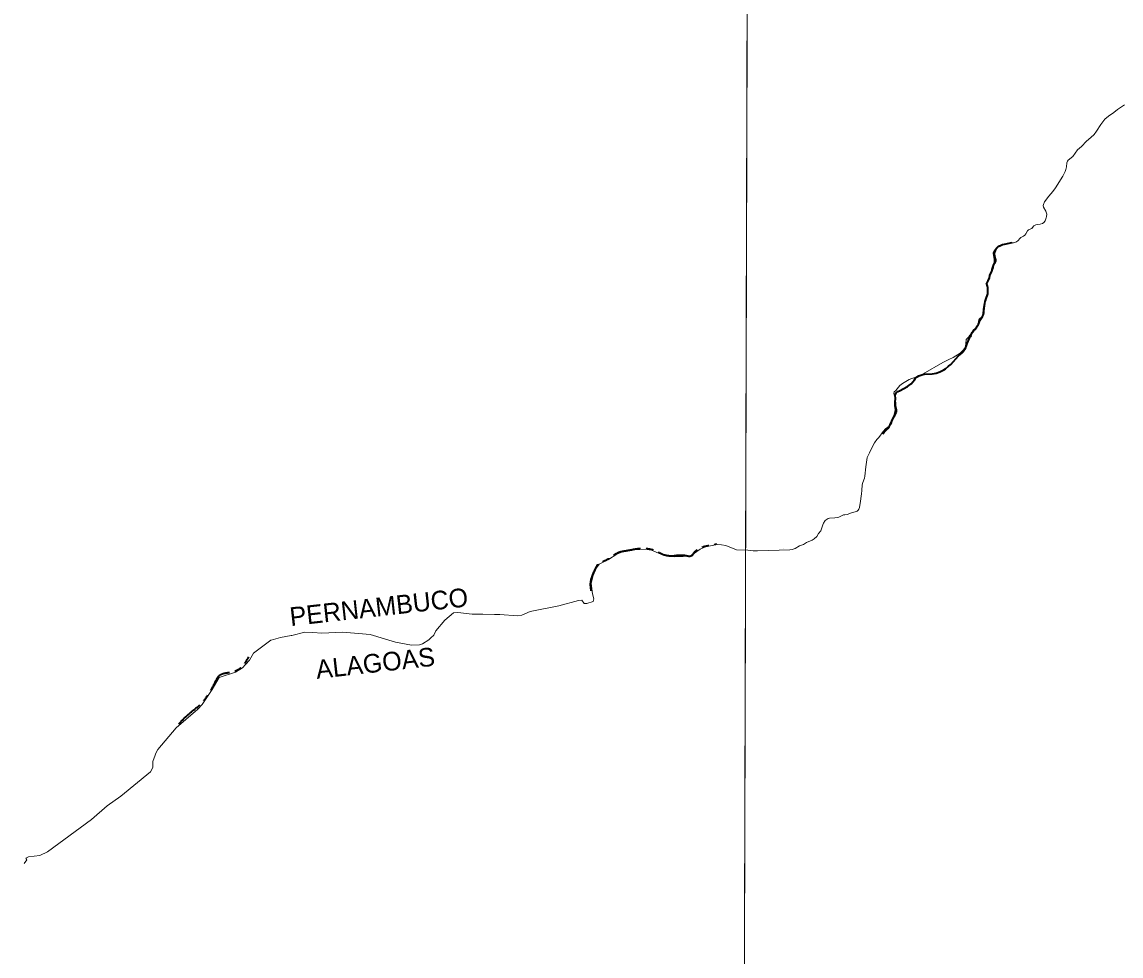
# Model space of a CAD drawing. Extents: x 553962 to 842807, y 8883888 to 9032388.
# Drawn here: x 582541 to 587242, y 8915855 to 8919850 of the extents above; entities that cross this region are included whole.
import ezdxf
from ezdxf.enums import TextEntityAlignment as Align

# ---------------------------------------------------------------- set-up
doc = ezdxf.new("R2010")
doc.units = 0
doc.header["$LTSCALE"] = 20
doc.header["$PDMODE"] = 32
doc.header["$PDSIZE"] = 10
doc.linetypes.add('LONG_DASH_SHORT_DASH', pattern=[9.9, 6, -1.2, 1.5, -1.2])
doc.layers.add('6', color=7, linetype='Continuous', lineweight=13)

msp = doc.modelspace()

# ---------------------------------------------------------------- linework, layer by layer
at = {"layer": '6', "linetype": 'LONG_DASH_SHORT_DASH', "lineweight": 35}
msp.add_line((585799.02, 8917597.87), (585799.32, 8917597.75), dxfattribs=at)
at = {"layer": '6'}
for points in [[(585656.26, 8924738.82), (585614.83, 8909969.81), (585573.59, 8896026.67)], [(586916.89, 8918999.45), (586921.84, 8919011.65), (586923.22, 8919017.85), (586923.79, 8919027.85), (586919.88, 8919040.65), (586909.88, 8919057.05), (586909.01, 8919064.25), (586909.36, 8919069.65), (586914.44, 8919080.45), (586932.36, 8919104.25), (586949.8, 8919125.05), (586961.45, 8919140.25), (586992.81, 8919190.24), (587002.74, 8919209.44), (587006.17, 8919218.44), (587008.87, 8919230.44), (587010.37, 8919247.44), (587012.94, 8919254.64), (587015.99, 8919258.64), (587034.99, 8919274.84), (587055.59, 8919302.44), (587071.97, 8919316.44), (587094.02, 8919340.44), (587112.31, 8919355.24), (587126.07, 8919368.84), (587137.1, 8919382.04), (587155.14, 8919411.03), (587172.63, 8919433.83), (587187.38, 8919446.23), (587211.42, 8919462.03), (587226.22, 8919474.83), (587234.77, 8919481.43), (587255.95, 8919495.03)], [(586679.62, 8918760.47), (586680.31, 8918772.47), (586692.49, 8918786.46), (586696.8, 8918798.86), (586696.92, 8918809.26), (586697.68, 8918812.66), (586699.34, 8918815.26), (586704.18, 8918820.06), (586707.65, 8918826.86), (586707.43, 8918834.46), (586702.57, 8918847.66), (586701.75, 8918857.46), (586703.12, 8918864.06), (586709.7, 8918881.26), (586720.99, 8918893.46), (586725.89, 8918895.66), (586766.08, 8918904.86), (586782.19, 8918905.06), (586794.27, 8918909.06), (586801.82, 8918914.66), (586808.77, 8918923.26), (586812.98, 8918927.26), (586824.34, 8918933.86), (586830.05, 8918938.46), (586834.77, 8918944.06), (586841.92, 8918955.86), (586845.78, 8918960.26), (586848.85, 8918962.45), (586859.67, 8918966.85), (586863.65, 8918970.45), (586869.35, 8918977.45), (586877.18, 8918981.65), (586883.62, 8918984.05), (586895.7, 8918985.25), (586905.68, 8918987.45), (586911.93, 8918992.65), (586916.89, 8918999.45)], [(586136.83, 8917879.9), (586143.92, 8917898.3), (586146.45, 8917907.1), (586150.67, 8917947.5), (586156.3, 8917986.5), (586166.18, 8918006.3), (586175.43, 8918028.7), (586186.59, 8918050.1), (586197.76, 8918063.5), (586206.05, 8918071.9), (586224.95, 8918098.7), (586234.78, 8918109.9), (586249.48, 8918120.49), (586256.8, 8918127.69), (586261.31, 8918135.69), (586262.8, 8918149.49), (586276.28, 8918165.49), (586281.76, 8918176.69), (586282.85, 8918182.29), (586282.85, 8918191.09), (586279.15, 8918209.49), (586279.06, 8918219.29), (586275.1, 8918241.29), (586270.84, 8918255.09), (586270.56, 8918261.29), (586271.46, 8918267.69), (586278.22, 8918274.09), (586295.85, 8918294.89), (586307.44, 8918303.69), (586335.05, 8918320.09), (586377.81, 8918336.69), (586395.11, 8918344.88), (586480.05, 8918393.48), (586505.67, 8918406.68), (586524.07, 8918414.88), (586554.02, 8918433.08), (586568.4, 8918447.28), (586570.64, 8918451.07), (586575.7, 8918463.87), (586578.3, 8918475.27), (586579.72, 8918491.87), (586595.52, 8918507.27), (586602.8, 8918522.27), (586607.5, 8918529.47), (586619.66, 8918540.07), (586627.31, 8918548.87), (586630.12, 8918555.47), (586632.32, 8918569.47), (586634.12, 8918575.07), (586636.68, 8918579.47), (586645.9, 8918589.07), (586648.8, 8918594.87), (586650.6, 8918604.27), (586653.47, 8918631.67), (586658.11, 8918644.67), (586665.33, 8918659.27), (586672.59, 8918692.67), (586672.57, 8918710.27), (586671.13, 8918715.67), (586665.94, 8918726.27), (586666.03, 8918731.47), (586667.98, 8918736.67), (586678.47, 8918755.07), (586678.47, 8918755.07), (586679.62, 8918760.47)], [(585824.41, 8917592.52), (585835.61, 8917593.52), (585848.49, 8917598.32), (585866.62, 8917609.52), (585883.02, 8917614.72), (585896.76, 8917622.92), (585921.04, 8917633.32), (585928.69, 8917638.52), (585940.33, 8917649.72), (585947.52, 8917662.72), (585957.13, 8917673.52), (585961.21, 8917682.51), (585965.86, 8917699.71), (585968.92, 8917706.91), (585976.02, 8917717.11), (585984.14, 8917723.91), (585988.59, 8917725.71), (585994.53, 8917727.11), (586017.59, 8917728.51), (586028.14, 8917729.91), (586035.33, 8917731.91), (586053.99, 8917741.31), (586060.58, 8917742.51), (586069.97, 8917742.71), (586088.92, 8917750.31), (586104.08, 8917754.31), (586112.49, 8917757.71), (586117.97, 8917762.11), (586120.73, 8917766.51), (586122.86, 8917773.11), (586126.88, 8917800.7), (586130.71, 8917821.1), (586131.44, 8917832.3), (586133.67, 8917846.3), (586134.34, 8917870.5), (586136.83, 8917879.9)], [(584946.04, 8917362.07), (584956.66, 8917362.07), (584984.54, 8917371.29), (584987.1, 8917382.27), (584980.72, 8917404.46), (584974.79, 8917448.59), (584983.71, 8917481.73), (584998.13, 8917514.82), (585010.09, 8917531.03), (585049.8, 8917550.45), (585085.67, 8917573.91), (585106.86, 8917581.97), (585162.09, 8917591.75), (585206.32, 8917594.73), (585224.1, 8917592.19)], [(585224.1, 8917592.19), (585233.4, 8917590.87), (585273.51, 8917573.05), (585302.34, 8917565), (585331.17, 8917562.88), (585406.47, 8917564.63)], [(585406.47, 8917564.63), (585417.47, 8917577.97), (585441.32, 8917595.18), (585463.78, 8917604.51), (585514.76, 8917615.55), (585533.14, 8917613.37)], [(585533.14, 8917613.37), (585551.5, 8917611.2), (585597.61, 8917591.76)], [(585597.61, 8917591.76), (585645.76, 8917591.33), (585655.09, 8917588.73), (585668.42, 8917587.53), (585687.47, 8917587.33), (585824.41, 8917592.52)], [(584562.46, 8917316.19), (584584.8, 8917316.03), (584660.99, 8917309.68), (584679.56, 8917312.24), (584715.25, 8917328.79), (584836.65, 8917352.14), (584920.83, 8917375.94), (584935.72, 8917377.6), (584946.04, 8917362.07)], [(584289.66, 8917215.32), (584302.15, 8917227.5), (584311.17, 8917245.51), (584349.83, 8917291.82), (584386.35, 8917322.08), (584405.06, 8917324.1), (584466.29, 8917316.89), (584511.78, 8917316.56), (584562.46, 8917316.19)], [(583605.63, 8917205.94), (583606.2, 8917206.36), (583647.12, 8917217.89), (583691.73, 8917225.13), (583694.72, 8917225.87)], [(583694.72, 8917225.87), (583751.27, 8917239.95), (583784.75, 8917238.18)], [(583784.75, 8917238.18), (583823.01, 8917236.17), (583913.88, 8917239.98), (584030.29, 8917229.37), (584139.1, 8917197.5), (584207.08, 8917184.76), (584241.06, 8917186.03), (584254.66, 8917190.71), (584281.9, 8917207.76), (584289.66, 8917215.32)], [(583497.19, 8917101.53), (583513.66, 8917119.7), (583530.69, 8917150.3), (583605.63, 8917205.94)], [(583374.42, 8917029.35), (583384.08, 8917046.74), (583454.08, 8917069.14), (583484.79, 8917087.86), (583497.19, 8917101.53)], [(583110.16, 8916714.53), (583112.94, 8916723.26), (583122.65, 8916738.7), (583200.61, 8916830.85), (583293.65, 8916911.16), (583311.91, 8916931.12), (583355.28, 8916994.89), (583374.42, 8917029.35)], [(583090.77, 8916642.8), (583100.41, 8916661.6), (583101.21, 8916686.36), (583110.16, 8916714.53)], [(582550.89, 8916250.96), (582561.61, 8916267.09), (582557.67, 8916274.19), (582569.71, 8916278.97), (582618.14, 8916284.93), (582650.66, 8916299.96), (582838.21, 8916439.15), (582906.14, 8916497.31), (582963.76, 8916539.16), (583090.77, 8916642.8)]]:
    msp.add_lwpolyline(points, dxfattribs=at)
msp.add_lwpolyline([(585645.85, 8921027.32), (574684.91, 8921064.73), (574653.9, 8910009.29), (585614.83, 8909969.81)], close=True, dxfattribs=at)
at = {"layer": '6', "linetype": 'LONG_DASH_SHORT_DASH', "lineweight": 35}
for points in [[(586698.23, 8918860.49), (586699.47, 8918868.42), (586701.64, 8918872.26), (586709.1, 8918881.65), (586716.24, 8918888.98), (586725.79, 8918894.05), (586735.18, 8918897.46), (586743.73, 8918899.72), (586775.47, 8918907.03)], [(586597.6, 8918506.68), (586605.88, 8918523.44), (586611.92, 8918529.87), (586617.3, 8918534), (586622.31, 8918538.95), (586623.43, 8918540.9), (586626.39, 8918548.82), (586631.33, 8918557.13), (586634.28, 8918565.07), (586637.85, 8918573.02), (586643.91, 8918581.69), (586648.8, 8918589.44), (586652.34, 8918595.64), (586654.74, 8918605.51), (586654.83, 8918613.81), (586656.72, 8918622.12), (586657.82, 8918638.18), (586659.7, 8918646.31), (586660.98, 8918654.24), (586663.51, 8918662.37), (586666.6, 8918670.86), (586668.92, 8918678.79), (586672.09, 8918687.11), (586672.32, 8918702.75), (586672.01, 8918712.02), (586671, 8918719.4), (586667.08, 8918727.62), (586666.89, 8918728.56), (586672.85, 8918741.98), (586679.05, 8918755.97), (586680.89, 8918764.72), (586683.42, 8918772.55), (586688.52, 8918781.85), (586690.29, 8918790.38), (586695.79, 8918807.89), (586701.35, 8918821.38), (586701.6, 8918825.45), (586701.38, 8918834.41), (586699.1, 8918851.1), (586698.23, 8918860.49)], [(586513.48, 8918384.68), (586547.15, 8918421.28), (586562.51, 8918435.19), (586568.84, 8918441.97), (586573.88, 8918450.34), (586577.19, 8918457.77), (586579.99, 8918465.89), (586583.2, 8918474.01), (586594.13, 8918497.99), (586597.6, 8918506.68)], [(586222.61, 8918087.88), (586223.87, 8918090.08), (586228.36, 8918096.06), (586236.46, 8918103.56), (586243.84, 8918110.94), (586250.22, 8918118.49), (586254.61, 8918126.44), (586260.85, 8918142.67), (586268.82, 8918158.24), (586272.83, 8918166.66), (586277.23, 8918183.12), (586278.11, 8918191.23), (586277.49, 8918199.54), (586276.02, 8918207.85), (586276.01, 8918223.72), (586276.64, 8918239.97), (586275.85, 8918254.02), (586276.74, 8918256.58), (586280.24, 8918263.9), (586287.4, 8918268.9), (586293.93, 8918272.71), (586327.79, 8918291.25), (586334.73, 8918295.44), (586343.46, 8918302.74), (586357.75, 8918319.53), (586363.11, 8918326.37), (586369.23, 8918332.04), (586377.34, 8918336.33), (586385.64, 8918339.59), (586393.58, 8918341.47), (586401.52, 8918342.93), (586433.78, 8918344.24), (586442.31, 8918345.77), (586450.62, 8918348.17), (586466.51, 8918353.82), (586474.8, 8918357.31), (586483.29, 8918361.59), (586490.34, 8918366.19), (586504.16, 8918377.48), (586513.48, 8918384.68)]]:
    msp.add_lwpolyline(points, dxfattribs=at)
for points in [[(584975.9, 8917417.46), (584975.54, 8917419.7), (584973.39, 8917450.52), (584981.27, 8917482.77), (584997.75, 8917518.61), (585007.78, 8917534.37), (585031.42, 8917545.13), (585065.09, 8917565.19), (585093.02, 8917581.68), (585130.99, 8917589.56), (585175.4, 8917597.44), (585208.36, 8917598.16), (585232.71, 8917594.58), (585252.05, 8917588.13), (585282.14, 8917573.08), (585320.82, 8917565.91)], [(585320.82, 8917565.91), (585379.56, 8917568.06), (585403.92, 8917567.34), (585406.07, 8917568.78), (585417.53, 8917582.39), (585451.2, 8917604.61), (585489.16, 8917612.5), (585512.14, 8917617.44)], [(583212.7, 8916848.62), (583254.21, 8916889.71), (583303.15, 8916930.22), (583370.64, 8917031.52), (583385.83, 8917055.16), (583431.39, 8917068.66), (583482.01, 8917092.3), (583511.31, 8917134.23)]]:
    msp.add_spline(points, degree=3, dxfattribs=at)
at = {"layer": '6'}
msp.add_point((586597.6, 8918506.68), dxfattribs=at)

# ---------------------------------------------------------------- texts
for s, p in [('PERNAMBUCO', (584071.74, 8917308.3)), ('ALAGOAS', (584056.62, 8917068.52))]:
    msp.add_text(s, height=80, rotation=6.379, dxfattribs=at).set_placement(p, align=Align.CENTER)

doc.saveas('drawing.dxf')
